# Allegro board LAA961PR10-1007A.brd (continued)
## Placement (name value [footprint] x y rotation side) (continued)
PC111  680P_0603_50V7K  [C_0603]  41.6 23.22 0 top
PC113  220U_6.3V_M  [C_APXK6R3ARA221MF451]  35.39 28.88 0 bottom
PC114  680P_0603_50V7K  [C_0603]  48.36 20.76 180 bottom
PC115  220U_6.3V_M  [C_APXK6R3ARA221MF451]  60.24 14.86 90 bottom
PC117  0.1U_0603_25V7K  [C_0603]  45.46 22.03 270 top
PC118  4.7U_0603_10V6K  [C_0603]  46.69 22.03 270 top
PC119  1U_0603_10V6K  [C_0603]  51.44 28.38 90 top
PC200  10U_0805_25V6K  [C_0805]  92.56 15.19 90 top
PC201  10U_0805_25V6K  [C_0805]  90.85 15.19 90 top
PC203  2200P_0402_50V7K  [C_0402]  93.96 15.9 90 top
PC204  0.22U_0603_16V7K  [C_0603]  82.68 17.75 180 bottom
PC205  22U_0805_6.3V6M  [C_0805]  80.67 15.13 270 bottom
PC206  0.1U_0402_25V6  [C_0402]  94.86 15.9 90 top
PC207  220U_D2_2VY_R17M  [C_D2]  111.06 15.24 0 bottom
PC208  680P_0603_50V7K  [C_0603]  83.64 13.62 0 bottom
PC209  1U_0603_10V6K  [C_0603]  76.11 21.42 270 bottom
PC211  1U_0603_10V6K  [C_0603]  74.84 20.02 90 bottom
PC212  0.033U_0402_16V7K  [C_0402]  74.84 14.2 270 bottom
PC213  100P_0402_50V8J  [C_0402]  71.83 14.21 180 bottom
PC214  .1U_0402_16V7K  [C_0402]  69.95 14.21 270 bottom
PC215  .1U_0402_16V7K  [C_0402]  73.18 18.11 180 bottom
PC300  2200P_0402_50V7K  [C_0402]  192.86 68.38 90 top
PC301  680P_0603_50V7K  [C_0603]  186.18 70.35 0 top
PC302  0.1U_0603_25V7K  [C_0603]  191.65 67.43 90 top
PC303  10U_0805_25V6K  [C_0805]  192.93 68.38 90 bottom
PC304  330P_0402_50V7K  [C_0402]  194.4 63.41 0 bottom
PC305  47U_0805_6.3V6M  [C_0805]  181.08 62.25 270 bottom
PC306  47U_0805_6.3V6M  [C_0805]  182.98 62.25 270 bottom
PC307  22U_0805_6.3VAM  [C_0805]  177.21 62.25 270 bottom
PC308  22U_0805_6.3VAM  [C_0805]  179.24 62.25 270 bottom
PC309  4.7U_0603_6.3V6K  [C_0603]  190.57 64.38 0 top
PC310  4.7U_0603_6.3V6K  [C_0603]  192.92 67.3 270 bottom
PC311  0.1U_0402_25V6  [C_0402]  195.35 66.27 180 bottom
PC400  1U_0402_6.3V6K  [C_0402]  195.11 77.66 270 bottom
PC401  4.7U_0805_6.3V6K  [C_0805]  197.89 77.08 180 bottom
PC402  .1U_0402_16V7K  [C_0402]  192.48 79.58 180 bottom
PC403  0.01U_0402_25V7K  [C_0402]  193.86 87.35 180 bottom
PC404  22U_0805_6.3V6M  [C_0805]  195.27 86.48 90 bottom
PC500  4700P_0603_50V7K  [C_0603]  89.92 98.86 0 top
PC501  .1U_0402_16V7K  [C_0402]  92.89 99.56 0 bottom
PC502  0.068U_0402_16V7K  [C_0402]  90.24 95.55 90 bottom
PC503  1000P_0402_50V7K  [C_0402]  93.59 110.23 0 bottom
PC504  0.1U_0402_25V6  [C_0402]  93.33 112.44 0 bottom
PC505  1U_0603_10V6K  [C_0603]  87.44 100.96 90 top
PC506  100P_0402_50V8J  [C_0402]  84.65 96.37 90 bottom
PC507  0.33U_0603_10V7K  [C_0603]  87.7 98.61 180 top
PC508  680P_0603_50V7K  [C_0603]  101.84 106.94 180 top
PC509  1U_0603_10V7K  [C_0603]  101.73 113.19 180 bottom
PC510  1U_0603_10V7K  [C_0603]  86.24 100.32 180 top
PC511  0.1U_0402_25V6  [C_0402]  82.43 102.53 90 bottom
PC512  1500P_0402_50V7K  [C_0402]  84.78 98.56 270 top
PC513  0.068U_0402_16V7K  [C_0402]  91.13 95.55 90 bottom
PC514  47P_0402_50V8J  [C_0402]  83.76 99.93 90 top
PC515  10U_0805_25V6K  [C_0805]  93.68 107.01 270 bottom
PC516  10U_0805_25V6K  [C_0805]  94.68 107.01 270 top
PC517  10U_0805_25V6K  [C_0805]  92.97 107.01 270 top
PC518  10U_0805_25V6K  [C_0805]  95.39 107.01 270 bottom
PC519  100U_D_20VM_R55M  [C_D]  90.2 106.99 90 bottom
PC520  2200P_0402_50V7K  [C_0402]  86.9 110.61 90 bottom
PC521  0.1U_0402_25V6  [C_0402]  94.5 109.35 180 bottom
PC700  0.1U_0603_25V7K  [C_0603]  52.54 42.61 270 top
PC701  1U_0603_25V6K  [C_0603]  39.88 41.72 0 top
PC702  0.1U_0402_25V6  [C_0402]  41.32 41.91 90 bottom
PC703  0.1U_0402_25V6  [C_0402]  41.29 42.83 180 top
PC704  10U_0805_25V6K  [C_0805]  17.92 51.82 90 top
PC705  10U_0805_25V6K  [C_0805]  19.62 51.82 90 top
PC706  10U_0805_25V6K  [C_0805]  21.32 51.82 90 top
PC707  10U_0805_25V6K  [C_0805]  23.02 51.82 90 top
PC708  22U_0805_25V6M  [C_0805]  24.74 51.83 90 top
PC709  10U_0805_25V6K  [C_0805]  41.85 44.02 90 top
PC710  1U_0603_10V6K  [C_0603]  35.78 45.85 180 bottom
PC711  0.1U_0402_25V6  [C_0402]  41.29 40.16 0 bottom
PC712  0.047U_0603_25V7K~D  [C_0603]  39.32 46.1 270 bottom
PC713  2200P_0402_50V7K  [C_0402]  38.66 55.13 180 top
PC714  22U_0805_25V6M  [C_0805]  38.85 53.81 180 top
PC715  22U_0805_25V6M  [C_0805]  38.86 50.4 180 top
PC716  22U_0805_25V6M  [C_0805]  41.85 47.43 270 bottom
PC717  22U_0805_25V6M  [C_0805]  38.86 52.1 180 top
PC718  100P_0402_50V8J  [C_0402]  42.2 38.41 180 bottom
PC719  100P_0402_50V8J  [C_0402]  39.62 39.6 270 top
PC721  1000P_0603_50V7K  [C_0603]  29.23 53.83 90 top
PC722  0.1U_0603_25V7K  [C_0603]  17.52 60.11 0 top
PC723  10U_0805_25V6K  [C_0805]  17.69 58.64 0 top
PC724  10U_0805_25V6K  [C_0805]  17.69 56.85 0 top
PC725  10U_0805_25V6K  [C_0805]  17.66 55.02 0 top
PC726  0.1U_0402_25V6  [C_0402]  36.44 42 180 top
PC727  0.1U_0402_25V6  [C_0402]  32.9 43.39 270 top
PC728  0.1U_0402_25V6  [C_0402]  35.52 41.11 0 top
PC729  1U_0603_25V6K  [C_0603]  35.59 40.07 0 top
PC732  0.1U_0402_25V6  [C_0402]  38.66 56.02 180 top
PC737  100P_0402_50V8J  [C_0402]  37.53 36.21 270 bottom
PC741  100P_0402_50V8J  [C_0402]  36.65 35.3 90 bottom
PC805  0.1U_0402_10V7K  [C_0402]  10.06 40.92 270 top
PC807  0.47U_0805_25V6K  [C_0805]  207.52 16.91 270 bottom
PC809  1500P_0402_50V7K  [C_0402]  196.45 15.22 0 bottom
PC810  0.1U_0402_10V7K  [C_0402]  7.69 24.07 270 top
PC813  0.1U_0603_50V4Z  [C_0603]  18.85 30.38 270 top
PC815  0.1U_0603_25V7K  [C_0603]  20.06 30.38 270 top
PC816  0.047U_0603_25V7M  [C_0603]  26.11 33.51 270 top
PC817  0.1U_0402_25V4Z~D  [C_0402]  26.05 34.46 0 top
PC900  22U_0805_6.3V6M  [C_0805]  98.36 97.36 0 bottom
PC901  22U_0805_6.3V6M  [C_0805]  101.65 97.35 0 bottom
PC902  22U_0805_6.3V6M  [C_0805]  104.99 97.36 0 bottom
PC903  22U_0805_6.3V6M  [C_0805]  108.41 97.34 0 bottom
PC904  22U_0805_6.3V6M  [C_0805]  111.61 97.34 0 bottom
PC913  22U_0805_6.3V6M  [C_0805]  114.85 99.5 0 bottom
PC914  22U_0805_6.3V6M  [C_0805]  118.15 99.5 0 bottom
PC915  22U_0805_6.3V6M  [C_0805]  104.96 99.57 0 bottom
PC916  22U_0805_6.3V6M  [C_0805]  108.26 99.61 0 bottom
PC917  22U_0805_6.3V6M  [C_0805]  111.66 99.52 0 bottom
PC966  220U 2.5V Y D2 ESR9M H1.9 SX  [C_D2]  113.88 102.75 0 bottom
PD1  -  [TVNST52302AB0_SOT523-3]  154.74 14.79 180 bottom
PD2  -  [TVNST52302AB0_SOT523-3]  152.75 14.79 180 bottom
PD3  BAS40CW SOT-323  [BAS40-05W_SC70-3]  214.25 51.87 90 bottom
PD4  SDMK0340L-7-F_SOD323-2~D  [RB751V-40_SOD323-2]  150.73 15.64 270 bottom
PD5  PESD5V0U2BT_SOT23-3  [AZC199-02SPR7G_SOT23-3]  67.92 119.84 90 bottom
PD702  SDMK0340L-7-F_SOD323-2~D  [SDMK0340L-7-F_SOD323-2]  45.99 46.74 180 top
PD704  SDMK0340L-7-F_SOD323-2~D  [SDMK0340L-7-F_SOD323-2]  49.74 46.68 270 top
PD705  SDMK0340L-7-F_SOD323-2~D  [SDMK0340L-7-F_SOD323-2]  48.01 46.68 270 top
PD800  -  [PDS5100H-13_POWERDI5-3]  10.53 55.59 270 bottom
PD808  -  [PDS5100H-13_POWERDI5-3]  202.59 18.7 180 top
PD813  SDMK0340L-7-F_SOD323-2~D  [SDMK0340L-7-F_SOD323-2]  4.03 27 0 top
PD815  -  [BAT54CW_SOT323-3]  17.34 42.33 180 top
PD817  -  [BAT54CW_SOT323-3]  11.03 33.96 90 top
PH500  100K_0402_1%_NCP15WF104F03RC  [R_0402]  99.49 107.2 0 bottom
PH501  10K_0402_1%_TSM0A103F34D1RZ  [R_0402]  108.13 106.61 0 top
PJP1  PAD-OPEN 1x3m  [JUMP_43X118]  73.79 104.95 270 bottom
PJP5  PAD-OPEN1x1m  [JUMP_43X39]  217.35 107.34 90 bottom
PJP6  PAD-OPEN1x2m  [JUMP_43X79]  214.37 64.12 270 top
PJP9  PAD-OPEN1X2m  [JUMP_43X79]  214.99 59.69 90 top
PJP10  PAD-OPEN1x1m  [JUMP_43X39]  196.71 72.76 0 top
PJP11  PAD-OPEN1x1m  [JUMP_43X39]  176.89 57.33 0 top
PJP12  PAD-OPEN1x1m  [JUMP_43X39]  196.36 112.25 270 top
PJP13  PAD-OPEN1x3m  [JUMP_43X118]  192.61 48.39 90 top
PJP14  PAD-OPEN1x1m  [JUMP_43X39]  174.06 104.52 270 top
PJP15  PAD-OPEN1x1m  [JUMP_43X39]  214.51 83.43 90 top
PJP16  PAD-OPEN1x1m  [JUMP_43X39]  200.85 60.57 270 top
PJP17  PAD-OPEN1x1m  [JUMP_43X39]  199.34 105.65 180 top
PJP19  PAD-OPEN1x1m  [JUMP_43X39]  201.56 30.66 180 top
PJP21  PAD-OPEN1x3m  [JUMP_43X118]  54.5 56.57 90 top
PJP22  PAD-OPEN1x3m  [JUMP_43X118]  56.97 64.19 90 top
PJP23  PAD-OPEN1x1m  [JUMP_43X39]  123.5 56.26 90 top
PJP24  PAD-OPEN1x1m  [JUMP_43X39]  140.15 99.63 270 bottom
PJP25  PAD-OPEN1x1m  [JUMP_43X39]  134.81 109.54 270 bottom
PJP26  PAD-OPEN1x1m  [JUMP_43X39]  22.01 10.18 180 top
PJP27  PAD-OPEN1x1m  [JUMP_43X39]  135.58 106.15 90 bottom
PJP28  PAD-OPEN1x1m  [JUMP_43X39]  143.66 97.76 90 bottom
PJP29  PAD-OPEN1x1m  [JUMP_43X39]  134.24 94.94 270 top
PJP32  PAD-OPEN1x3m  [JUMP_43X118]  187.35 49.49 270 top
PJP36  PAD-OPEN1x1m  [JUMP_43X39]  133.72 106.32 180 top
PJP51  PAD-OPEN1x1m  [JUMP_43X39]  129.85 100.61 180 top
PJP66  PAD-OPEN1x1m  [JUMP_43X39]  201.62 107.51 90 top
PJP100  PAD-OPEN 1x3m  [JUMP_43X118]  37.76 15.54 0 bottom
PJP101  PAD-OPEN 1x3m  [JUMP_43X118]  65.23 19.09 0 bottom
PJP102  PAD-OPEN 1x3m  [JUMP_43X118]  35.96 28.59 90 top
PJP200  PAD-OPEN 1x2m~D  [JUMP_43X79]  91.95 12.39 90 top
PJP201  PAD-OPEN1x1m  [JUMP_43X39]  81.41 16.69 0 top
PJP202  PAD-OPEN1x1m  [JUMP_43X39]  76.55 13.9 270 bottom
PJP203  JUMP_1x3m  [JUMP_43X118]  108.27 18.94 90 bottom
PJP204  JUMP_1x3m  [JUMP_43X118]  112.65 18.94 90 bottom
PJP300  -  [JUMP_43X118]  173.7 62.21 180 bottom
PJP302  PAD-OPEN 1x2m~D  [JUMP_43X79]  196.03 68.7 180 bottom
PJP400  PAD-OPEN1x1m  [JUMP_43X39]  197.3 74.46 90 bottom
PJP401  PAD-OPEN1x1m  [JUMP_43X39]  196.84 86.8 0 bottom
PJP500  PAD-OPEN 4x4m  [JUMP_43X118]  79.26 101.92 90 bottom
PJP700  PAD-OPEN 4x4m  [JUMP_43X118-NPM]  43.96 50.68 180 bottom
PJP701  PAD-OPEN1x1m  [JUMP_43X39]  35.05 43.59 180 top
PJPDC1  ACES_50299-0050N-001  [ACES_50299-0050N-001_5P]  81.55 116.15 270 bottom
PL1  FBMJ4516HS720NT_2P~D  [TAIYO_FBMJ4516HS720NT_2P]  156.93 14.02 0 bottom
PL2  FBMJ4516HS720NT_2P~D  [TAIYO_FBMJ4516HS720NT_2P]  156.93 16.41 0 bottom
PL3  BLM15AG102SN1D_2P  [MURAT_BLM15AG102SN1D_2P]  77.83 113.45 90 top
PL4  FBMJ4516HS720NT_2P  [TAIYO_FBMJ4516HS720NT_2P]  69.34 105.34 270 bottom
PL100  1UH +-20% 6.6A  [L_5X5X3_M_2P-NPM]  36.13 15.48 0 bottom
PL101  2.2UH_7.8A_20%  [PANAS_ETQP3W2R2WFN_2P]  36.18 21.83 180 bottom
PL102  3.3UH_6.3A_20%  [PANAS_ETQP3W2R2WFN_2P]  48.65 16.34 180 bottom
PL200  1UH_11A_20%  [PANAS_ETQP3W2R2WFN_2P]  93.53 16.37 0 bottom
PL301  0.68UH +-20% 7.9A  [L_5X5X3_M_2P]  185.99 67.43 180 bottom
PL500  0.15UH_PCME064T-R15MS0R667_36A_20%  [PANAS_ETQP4LR15AFM_4P]  111.92 108.78 180 bottom
PL501  FBMA-L11-453215800LMA90T_2P  [FBMA-L11-453215800LMA90T_2P-NPM]  79.27 100.56 90 bottom
PL700  1UH +-20% 6.6A  [L_5X5X3_M_2P]  41.28 50.68 0 bottom
PL701  3.3UH +-20% PIMB104T 10A  [TOKO_FDVE1040-H-3R3M-P3_2P]  20.31 47.98 0 bottom
PQ1  DMG2301U-7 1P SOT23-3  [FDN338P_NL_SOT23-3]  147.67 14.15 180 bottom
PQ2  -  [FDV301N-G_SOT23-3]  70.98 112.27 0 top
PQ3  MMST3904-7-F_SOT323~D  [MMST3904-7-F_SOT323-3]  71.64 110.22 180 top
PQ4  -  [FDMC6679AZ_MLP8-5]  48.38 41.01 270 bottom
PQ6  DCX124EK-7-F PNP/NPN_SC74-6~D  [IMD2AT-108_SC74-6]  69.28 96.07 270 top
PQ100  -  [SIS412DN-T1-GE3_POWERPAK8-5]  39.11 20.18 180 top
PQ101  -  [SIS412DN-T1-GE3_POWERPAK8-5]  53.19 16.36 180 top
PQ102  -  [SI7716ADN-T1-GE3_POWERPAK8-5]  43.58 19.82 90 top
PQ103  -  [SI7716ADN-T1-GE3_POWERPAK8-5]  48.03 20.09 270 top
PQ200  -  [SIS412DN-T1-GE3_POWERPAK8-5]  85.95 19.12 180 top
PQ201  -  [SI7716ADN-T1-GE3_POWERPAK8-5]  90.55 18.99 90 top
PQ700  -  [SI4835DDY-T1-GE3_SO8]  49.38 46.79 270 bottom
PQ701  -  [NTR4502PT1G_SOT23-3]  53.65 38.73 90 top
PQ702  -  [NTR4502PT1G_SOT23-3]  53.74 34.74 90 top
PQ703  SI3993CDV-T1-GE3_TSOP6  [NTGD4161PT1G_TSOP6]  59.11 43.06 180 top
PQ705  -  [AON6970_DFN5X6D-8-7]  37.59 47.14 180 bottom
PQ712  -  [DMN65D8LW-7_SOT323-3]  7.44 21 270 top
PQ800  -  [SI4835DDY-T1-GE3_SO8]  14.29 57.53 180 top
PQ806  -  [DMN65D8LDW-7_SOT363-6]  11 37.15 270 top
PQ810  -  [FDS6679AZ-G_SO8]  205.37 21.14 270 bottom
PQ813  -  [DMN65D8LDW-7_SOT363-6]  12.01 29.52 0 top
PQ814  -  [NTR4502PT1G_SOT23-3]  6.86 30.19 270 top
PQ815  -  [FDS6679AZ-G_SO8]  197.81 21.14 270 bottom
PQ816  -  [DMN65D8LW-7_SOT323-3]  201.87 9.62 0 top
PQ817  -  [DMN65D8LDW-7_SOT363-6]  13.72 23.2 90 top
PQ826  -  [FDMC6679AZ_MLP8-5]  198.81 24.64 270 top
PQ829  DMG2301U-7 1P SOT23-3  [SI2301CDS-T1-GE3_SOT23-3]  9.29 34.15 90 top
PQ832  -  [DMN65D8LW-7_SOT323-3]  4.41 35.55 0 top
PR1  1K_0402_5%  [R_0402]  213.27 50.16 180 bottom
PR2  100K_0402_5%  [R_0402]  150.09 16.97 0 bottom
PR6  0_0402_5%  [R0402_0OHM]  146.08 18.05 0 bottom
PR7  0_0402_5%  [R_0402]  68.47 113.41 90 top
PR8  2.2K_0402_5%  [R_0402]  71.25 118.04 0 top
PR9  33_0402_5%  [R_0402]  71.24 117.1 0 top
PR10  100K_0402_1%  [R_0402]  69.38 110.56 90 top
PR11  10K_0402_1%  [R_0402]  74.05 116.17 180 top
PR12  15K_0402_1%  [R_0402]  69.38 108.78 90 top
PR13  10K_0402_5%  [R_0402]  72.15 116.2 180 top
PR14  1M_0402_5%  [R_0402]  70.98 101.02 0 top
PR15  100K_0402_5%  [R_0402]  46.09 40.69 0 top
PR16  4.7K_0805_5%  [R_0805]  68.39 101.18 90 top
PR17  10K_0402_5%  [R_0402]  71.9 101.91 180 top
PR18  1M_0402_5%  [R_0402]  73.27 97.97 0 top
PR100  6.49K_0402_1%  [R_0402]  44.52 29.2 270 top
PR101  15K_0402_1%  [R_0402]  49.44 28.9 90 top
PR102  10K_0402_1%  [R_0402]  45.42 29.01 270 top
PR103  0_0402_5%  [R0402_0OHM]  47.67 29.78 270 top
PR104  10K_0402_1%  [R_0402]  48.55 28.32 90 top
PR105  20K_0402_1%  [R_0402]  43.63 29.19 270 top
PR106  16.9K_0402_1%  [R_0402]  50.33 29.85 270 top
PR107  100K_0402_1%  [R_0402]  42.65 29.16 180 top
PR108  0_0402_5%  [R0402_0OHM]  41.73 28.27 0 top
PR109  2.2_0603_5%  [R_0603]  50.99 24.76 0 top
PR110  2.2_0603_5%  [R_0603]  41.54 24.92 0 top
PR111  4.7_1206_5%  [R_1206]  37.67 24.22 0 top
PR112  4.7_1206_5%  [R_1206]  52.21 20.89 180 bottom
PR113  0_0402_5%  [R0402_0OHM]  52.52 29.14 270 top
PR114  200_0402_1%  [R_0402]  50.92 27.17 0 top
PR200  2.2_0603_5%  [R_0603]  82.69 16.49 180 bottom
PR201  19.6K_0402_1%  [R_0402]  77.21 21.45 270 bottom
PR202  5.1_0603_5%  [R_0603]  72.91 19.7 0 top
PR203  4.7_1206_5%  [R_1206]  84.57 17.72 270 bottom
PR204  0_0603_5%  [R_0603]  76.9 19.61 180 top
PR205  8.06K_0402_1%  [R_0402]  71.83 15.1 180 bottom
PR206  768K_0402_1%  [R_0402]  72.27 20.78 0 bottom
PR207  0_0402_5%  [R0402_0OHM]  73.18 19.89 270 bottom
PR209  10K_0402_1%  [R_0402]  71.83 13.33 180 bottom
PR210  0_0402_5%  [R0402_0OHM]  72.27 17.22 0 bottom
PR303  1M_0402_1%  [R_0402]  187.13 64.04 270 bottom
PR305  4.7_1206_5%  [R_1206]  186.63 68.6 180 top
PR306  0_0402_5%  [R_0402]  190.69 63.4 90 bottom
PR307  7.5K_0402_1%  [R_0402]  193.46 63.41 90 bottom
PR308  0_0402_5%  [R_0402]  191.63 64.3 270 bottom
PR309  1K_0402_5%  [R_0402]  195.29 64.29 180 bottom
PR310  10K_0402_1%  [R_0402]  192.59 64.32 270 bottom
PR312  0_0603_5%  [R_0603]  190.5 68.7 180 top
PR313  0_0402_5%  [R0402_0OHM]  188.9 63.12 90 bottom
PR315  100K_0402_1%  [R_0402]  189.8 63.12 90 bottom
PR400  100K_0402_5%  [R_0402]  191.57 77.78 0 bottom
PR401  47K_0402_5%  [R_0402]  192.48 78.68 180 bottom
PR402  8.66K_0402_1%  [R_0402]  193.86 86.43 180 bottom
PR403  10K_0402_1%  [R_0402]  192.03 87.38 270 bottom
PR500  75_0402_1%  [R_0402]  92.89 98.16 0 bottom
PR501  365K_0402_1%  [R_0402]  92.84 99.38 270 top
PR502  75_0402_1%  [R_0402]  92.89 101.4 0 bottom
PR503  681K_0402_1%  [R_0402]  92.89 102.29 0 bottom
PR504  36.5K_0402_1%  [R_0402]  92.89 103.18 0 bottom
PR505  10K_0402_5%  [R_0402]  93.8 101.4 180 top
PR506  39K_0402_1%  [R_0402]  90.16 99.94 0 top
PR507  150K_0402_1%  [R_0402]  90.16 100.83 0 top
PR508  100K_0402_1%  [R_0402]  90.16 101.72 0 top
PR509  20K_0402_1%  [R_0402]  90.16 102.61 0 top
PR510  39K_0402_5%~N  [R_0402]  90.22 97.78 0 top
PR511  10K_0402_5%  [R_0402]  93.8 97.27 180 bottom
PR512  2.15K_0402_1%  [R_0402]  107.25 107.48 90 top
PR513  75_0402_1%  [R_0402]  88.52 102.37 270 top
PR514  20K_0402_1%  [R_0402]  108.14 107.48 90 top
PR515  3.01K_0402_1%  [R_0402]  109.03 107.48 90 top
PR516  1.91K_0402_1%  [R_0402]  88.14 103.42 90 bottom
PR517  2.2_0603_5%  [R_0603]  94.48 111.31 180 bottom
PR518  2M_0402_1%  [R_0402]  95.07 101.43 270 top
PR519  1_0603_5%  [R_0603]  87.19 104.24 180 bottom
PR520  0_0402_5%  [R0402_0OHM]  90.16 104.33 270 bottom
PR521  4.87K_0402_1%  [R_0402]  84.88 98.59 90 bottom
PR522  4.7_1206_5%  [R_1206]  102.3 110.93 270 top
PR523  10K_0402_5%  [R_0402]  83.76 96.37 90 bottom
PR524  2M_0402_1%  [R_0402]  95.96 99.62 180 top
PR525  27K_0402_1%  [R_0402]  95.96 100.51 90 top
PR526  10_0603_1%  [R_0603]  83.82 99.61 270 bottom
PR527  54.9_0402_1%  [R_0402]  83.3 102.04 0 bottom
PR528  75_0402_1%  [R_0402]  83.3 102.92 0 bottom
PR529  110_0402_1%  [R_0402]  83.3 103.84 0 bottom
PR531  0_0402_5%  [R0402_0OHM]  97.86 95.48 90 top
PR532  0_0402_5%  [R0402_0OHM]  96.97 95.48 90 top
PR534  0_0402_5%  [R0402_0OHM]  82.41 100.28 90 bottom
PR535  4.75K_0402_1%  [R_0402]  83.89 97.64 90 top
PR536  0_0402_5%  [R0402_0OHM]  90.05 104.4 270 top
PR539  0_0402_5%  [R0402_0OHM]  88.14 103.94 90 top
PR700  0_0402_5%  [R0402_0OHM]  49.98 48.43 90 bottom
PR701  0.01_1206_1%  [R_1206_4P-D]  48.49 53.36 270 bottom
PR702  0_0402_5%  [R0402_0OHM]  51.5 42.14 270 top
PR703  100_0402_1%  [R_0402]  44.34 42.84 270 top
PR704  0_0402_5%  [R0402_0OHM]  43.48 41.93 180 top
PR705  0_0402_5%  [R0402_0OHM]  43.48 42.82 180 top
PR706  100K_0402_1%  [R_0402]  55.95 41.16 270 top
PR707  100K_0402_1%  [R_0402]  55.92 42.59 90 top
PR708  10_1206_5%  [R_1206]  46.12 44.81 180 top
PR709  0_0402_5%  [R0402_0OHM]  56.11 44.45 0 top
PR710  34K_0402_1%  [R_0402]  42.19 41.04 180 bottom
PR711  6.49K_0402_1%  [R_0402]  41.29 39.28 0 bottom
PR712  2.2_0603_5%  [R_0603]  36.83 45.79 0 bottom
PR713  100K_0402_1%  [R_0402]  41.49 37.7 90 top
PR714  0_0402_5%  [R0402_0OHM]  41.48 39.68 90 top
PR715  154K_0402_1%  [R_0402]  40.54 38.66 90 top
PR716  0_0402_5%  [R0402_0OHM]  42.28 37.53 180 bottom
PR717  0_0402_5%  [R0402_0OHM]  39.69 37.23 180 bottom
PR718  0_0402_5%  [R0402_0OHM]  39.63 36.36 90 top
PR720  0_0402_5%  [R0402_0OHM]  38.74 36.36 90 top
PR721  0.01_1206_1%  [R_1206_4P-D]  16.5 53.72 270 bottom
PR722  4.02K_0402_1%  [R_0402]  33.54 41.61 180 top
PR723  10_0603_1%  [R_0603]  34.08 40.55 180 top
PR725  1K_0402_1%  [R_0402]  33.23 39.51 0 top
PR726  4.7_1206_5%  [R_1206]  30.51 54.36 0 top
PR728  0_0402_5%  [R0402_0OHM]  33.23 38.64 0 top
PR729  154K_0402_1%  [R_0402]  35.55 39.03 0 top
PR737  649K_0402_1%  [R_0402]  39.32 35.29 90 bottom
PR738  3M_0402_5%  [R_0402]  37.54 37.22 180 bottom
PR740  10K_0402_1%  [R_0402]  35.79 36.36 180 bottom
PR743  0_0402_5%  [R0402_0OHM]  35.79 37.23 180 bottom
PR745  100K_0402_1%  [R_0402]  38.44 36.2 270 bottom
PR788  20K_0402_1%  [R_0402]  38.74 39.6 270 top
PR799  10K_0402_1%  [R_0402]  34.06 42.71 180 bottom
PR810  100K_0402_5%  [R_0402]  9.98 38.99 270 top
PR811  0_0402_5%  [R0402_0OHM]  206.01 15.97 270 bottom
PR812  0_0402_5%  [R0402_0OHM]  5.88 37.43 90 top
PR813  100K_0402_5%  [R_0402]  204.74 16.13 180 bottom
PR814  330K_0402_5%  [R_0402]  201.95 16.12 180 bottom
PR815  100K_0402_5%  [R_0402]  204.74 15.05 180 bottom
PR816  0_0402_5%  [R_0402]  204.24 14.2 270 bottom
PR818  100K_0402_5%  [R_0402]  197.35 16.13 180 bottom
PR819  100K_0402_5%  [R_0402]  12.25 21.81 0 top
PR822  10K_0402_5%  [R_0402]  197.37 14.24 270 bottom
PR826  100K_0402_5%  [R_0402]  10.7 29.95 270 top
PR827  100K_0402_5%  [R_0402]  10.7 30.88 90 top
PR828  10K_0402_5%  [R_0402]  5.46 32.57 270 top
PR829  100K_0402_5%  [R_0402]  13.4 27.16 90 top
PR830  100K_0402_5%  [R_0402]  7.1 36.55 180 top
PR831  100_0603_1%  [R_0603]  14.73 34.31 0 top
PR832  100_0603_1%  [R_0603]  15.84 35.42 90 top
PR835  47_0805_5%~D  [R_0805]  17.35 28.58 90 top
PR838  100_0603_1%  [R_0603]  15.83 37.8 90 top
PR842  0_0402_5%  [R0402_0OHM]  21.14 29.54 90 top
PR843  0_0402_5%  [R0402_0OHM]  18.3 40.62 90 top
PR844  10K_0402_5%  [R_0402]  15.62 42.54 90 top
PR845  0_0402_5%  [R0402_0OHM]  19.19 40.62 90 top
PR846  100K_0402_5%  [R_0402]  22.16 28.12 180 top
PR847  100_0603_1%  [R_0603]  22.19 29.45 90 top
PR848  0_0402_5%  [R0402_0OHM]  20.78 40.61 90 top
PR850  0_0402_5%  [R0402_0OHM]  22.56 40.61 90 top
PR851  0_0402_5%  [R0402_0OHM]  23.26 29.61 90 top
PR853  0_0402_5%  [R0402_0OHM]  11.61 28.06 0 top
PR854  0_0402_5%  [R0402_0OHM]  23.47 40.61 90 top
PR855  0_0402_5%  [R0402_0OHM]  24.15 29.61 90 top
PR857  0_0402_5%  [R0402_0OHM]  25.97 38.76 0 top
PR858  1M_0402_5%  [R_0402]  21.67 41.52 270 top
PR859  0_0402_5%  [R0402_0OHM]  25.97 39.64 0 top
PR860  100_0603_1%  [R_0603]  26.08 36.81 0 top
PR863  0_0402_5%  [R_0402]  24.4 40.59 90 top
PR864  100K_0402_5%  [R_0402]  23.29 28.12 0 top
PR874  1M_0402_5%  [R_0402]  25.97 37.87 0 top
PR895  0_0402_5%  [R0402_0OHM]  8.88 36.55 180 top
PRP2  100_0804_8P4R_5%  [RP_0804_8P4R]  156.56 19.73 180 bottom
PT1  PAD~D  [TPC12]  190.74 88.93 0 top
PT2  PAD~D  [TPC12]  190.19 90.1 0 top
PT3  PAD~D  [TPC12]  202.31 107.79 180 bottom
PU1  TS5A63157DCKR_SC70-6~D  [TS5A63157DCKR_SC70-6]  68.66 116.38 0 top
PU100  -  [TPS51285BRUKR_QFN20_3X3]  47.54 26.56 180 top
PU200  -  [RT8207MZQW_WQFN20_3X3]  78.15 15.51 180 bottom
PU300  -  [SYX198DQNC_QFN10_3X3]  188.88 66.54 0 bottom
PU400  -  [APL5930KAI-TRG_SO8]  193.8 84.45 0 bottom
PU500  TPS51624RSM_QFN32_4X4  [TPS51622RSM_QFN32_4X4]  87.35 102.14 0 bottom
PU501  -  [CSD97374CQ4M_SON8_3P5X4P5]  99.32 111.72 270 bottom
PU700  BQ24777RUYR_WQFN28_4x4  [BQ24715URUYR_WQFN28_4X4]  39.77 42.29 180 bottom
PU800  CD3301BRHHR_QFN36_6X6~D  [CD3301RHHR_QFN36_6X6]  18.91 32.64 0 top
PU804  TC7SH08FU_SSOP5~D  [TC7SH08FU_SSOP5]  6.95 38.87 270 top
PU806  TC7SH08FU_SSOP5~D  [TC7SH08FU_SSOP5]  10.72 23.23 90 top
QA1  -  [L2N7002WT1G_SC-70-3]  201.12 65.02 0 top
QA2  -  [DMN66D0LDW-7_SOT363-6]  217.94 75.77 0 top
QA3  -  [DMN66D0LDW-7_SOT363-6]  208.11 60.59 90 top
QC1  -  [DMN66D0LDW-7_SOT363-6]  158.06 68.43 90 bottom
QD1  -  [L2N7002WT1G_SC-70-3]  98.43 10.21 0 top
QE2  -  [DMN66D0LDW-7_SOT363-6]  194.12 83.76 270 top
QE3  MMBT3904WT1G_SC70-3~D  [MMBT3904WT1G_SC70-3]  113.95 80.69 270 top
QE4  -  [MMBT3904WT1G_SC70-3]  199.9 99.5 90 top
QE5  MMBT3904WT1G_SC70-3~D  [MMBT3904WT1G_SC70-3]  204.43 35.6 180 bottom
QE6  MMBT3904WT1G_SC70-3~D  [MMBT3904WT1G_SC70-3]  84.43 95.56 90 top
QE7  MMBT3904WT1G_SC70-3~D  [MMBT3904WT1G_SC70-3]  195.82 104.23 0 bottom
QL1  -  [DMN66D0LDW-7_SOT363-6]  208.4 124.11 270 top
QL2  -  [DMN66D0LDW-7_SOT363-6]  217.95 122 270 top
QN1  -  [DMN66D0LDW-7_SOT363-6]  215.71 111.72 180 top
QV1  -  [AO6405_TSOP6]  94.69 113.88 180 top
QV2  -  [L2N7002WT1G_SC-70-3]  82.05 112.05 270 top
QV7  -  [L2N7002WT1G_SC-70-3]  125.98 124.12 180 bottom
QV8  -  [LP2301ALT1G_SOT23-3]  122.24 120.64 180 bottom
QV9  -  [L2N7002WT1G_SC-70-3]  136.72 118.99 90 bottom
QV10  -  [L2N7002WT1G_SC-70-3]  161.93 98.8 270 bottom
QV501  -  [L2N7002WT1G_SC-70-3]  241.06 132.26 270 top
QV502  -  [L2N7002WT1G_SC-70-3]  234.51 125.15 0 top
QV700  -  [DMN66D0LDW-7_SOT363-6]  168.75 116.66 90 bottom
QZ1  -  [LP2301ALT1G_SOT23-3]  104.74 119.48 270 top
QZ2  -  [DMN66D0LDW-7_SOT363-6]  163.85 93.85 180 bottom
QZ3  -  [DMN66D0LDW-7_SOT363-6]  191.58 114.48 90 top
QZ4  -  [DDTA114EUA-7-F_SOT323-3]  191.51 112.65 90 top
QZ5  -  [DMN66D0LDW-7_SOT363-6]  190.63 120.13 270 top
QZ6  -  [SI3456DDV-T1-GE3_TSOP6]  133.91 100.71 90 top
QZ7  -  [DMN66D0LDW-7_SOT363-6]  191.9 126.99 270 top
QZ9  -  [DDTA114EUA-7-F_SOT323-3]  199.43 123.71 90 top
QZ10  -  [DMN66D0LDW-7_SOT363-6]  164.35 80.08 0 top
QZ11  -  [DMN66D0LDW-7_SOT363-6]  206.16 54.84 0 bottom
QZ12  -  [DDTA114EUA-7-F_SOT323-3]  198.3 119.48 90 top
QZ14  -  [DMN66D0LDW-7_SOT363-6]  193.61 120.13 270 top
R6  10_0402_5%  [R_0402]  161.36 125.2 270 bottom
R41  10_0402_5%  [R_0402]  165.1 125.23 270 bottom
R252  33_0402_5%  [R_0402]  144.47 124.31 90 bottom
R253  33_0402_5%  [R_0402]  145.35 124.31 90 bottom
R254  33_0402_5%  [R_0402]  146.05 130.43 270 top
R255  33_0402_5%  [R_0402]  146.24 124.31 90 bottom
R256  33_0402_5%  [R_0402]  146.94 130.43 270 top
R257  33_0402_5%  [R_0402]  147.13 124.31 90 bottom
R258  33_0402_5%  [R_0402]  149.61 130.43 270 top
R259  33_0402_5%  [R_0402]  143.58 124.31 90 bottom
R260  33_0402_5%  [R_0402]  144.27 130.43 270 top
R261  33_0402_5%  [R_0402]  145.16 130.43 270 top
R262  33_0402_5%  [R_0402]  147.83 130.43 270 top
R263  33_0402_5%  [R_0402]  148.02 124.31 90 bottom
R264  33_0402_5%  [R_0402]  148.72 130.43 270 top
R265  33_0402_5%  [R_0402]  148.91 124.31 90 bottom
R266  33_0402_5%  [R_0402]  149.8 124.31 90 bottom
R267  33_0402_5%  [R_0402]  150.5 130.43 270 top
R268  100K_0402_5%  [R_0402]  152.21 125.23 270 bottom
R271  100K_0402_5%  [R_0402]  150.51 137.15 180 top
R272  100K_0402_5%  [R_0402]  179.34 124.01 180 bottom
R273  10_0402_5%  [R_0402]  175.47 125.38 270 bottom
RA3  0_0603_5%  [R0603_0OHM]  208.59 77.13 270 top
RA4  0_0603_5%  [R0603_0OHM]  214.72 77.16 270 top
RA5  2.2K_0402_5%  [R_0402]  211.7 68.88 0 top
RA6  2.2K_0402_5%  [R_0402]  211.7 69.75 0 top
RA7  24.9_0402_1%  [R_0402]  211.65 72 0 top
RA8  24.9_0402_1%  [R_0402]  211.65 71.12 0 top
RA9  33_0402_5%  [R_0402]  201.09 69.98 0 top
RA12  1K_0402_5%  [R_0402]  199.8 67.34 180 top
RA13  1K_0402_5%  [R_0402]  199.8 66.47 180 top
RA14  33_0402_5%  [R_0402]  201.69 74.54 180 top
RA17  33_0402_5%  [R_0402]  201.75 71.33 180 top
RA18  10K_0402_5%  [R_0402]  200.28 77.3 180 top
RA21  100K_0402_5%  [R_0402]  215.78 77.4 0 top
RA24  4.7K_0402_5%  [R_0402]  213.39 72 0 top
RA25  4.7K_0402_5%  [R_0402]  213.39 71.12 0 top
RA26  100K_0402_5%  [R_0402]  204.28 61.05 0 top
RA27  200K_0402_5%  [R_0402]  209.96 61.99 180 top
RA28  100K_0402_5%  [R_0402]  204.28 60.16 0 top
RA29  100K_0402_5%  [R_0402]  209.96 61.1 180 top
RA30  22_0402_5%  [R_0402]  203.3 64.91 90 top
RA31  22_0402_5%  [R_0402]  204.18 64.91 90 top
RA32  33_0402_5%  [R_0402]  205.04 64.91 90 top
RA35  0_0402_5%  [R0402_0OHM]  217.44 66.45 0 top
RA36  0_0402_5%  [R0402_0OHM]  220.27 75.56 90 top
RA37  0_0402_5%  [R0402_0OHM]  210.16 63.95 270 top
RA38  100K_0402_5%  [R_0402]  203.41 60.15 90 top
RA39  0_0805_5%  [R0805_0OHM]  200.66 81.32 270 top
RA44  100K_0402_5%  [R_0402]  209.29 62.88 90 top
RA45  0_0402_5%  [R0402_0OHM]  211.05 61.75 270 top
RC1  330K_0402_5%  [R_0402]  163.15 53.95 90 top
RC2  1K_0402_5%  [R_0402]  121.57 14.38 270 bottom
RC4  0_0402_5%  [R0402_0OHM]  142.5 64.2 270 bottom
RC7  10M_0402_5%  [R_0402]  142.5 62.3 270 bottom
RC8  20K_0402_5%  [R_0402]  164.07 65.38 180 top
RC9  1M_0402_5%  [R_0402]  164.07 61.85 180 top
RC10  20K_0402_5%  [R_0402]  164.07 62.73 180 top
RC11  1K_0402_5%  [R_0402]  133.01 61.7 90 bottom
RC17  3.01K_0402_1%  [R_0402]  131 94.34 90 top
RC18  1K_0402_1%  [R_0402]  76.82 76.64 0 top
RC19  33_0402_5%  [R_0402]  134.79 61.7 90 bottom
RC20  33_0402_5%  [R_0402]  164.06 59.79 180 top
RC21  51_0402_5%  [R_0402]  94.41 77.02 180 top
RC22  33_0402_5%  [R_0402]  136.7 61.7 90 bottom
RC23  33_0402_5%  [R_0402]  135.81 61.7 90 bottom
RC25  1K_0402_5%  [R_0402]  93.84 91.91 180 bottom
RC26  0_0402_5%  [R0402_0OHM]  156.85 78.21 90 bottom
RC27  0_0402_5%  [R_0402]  156.91 81.28 270 bottom
RC29  1K_0402_5%  [R_0402]  175.53 76.14 180 top
RC30  0_0402_5%  [R0402_0OHM]  154.8 72.19 0 bottom
RC31  1K_0402_5%  [R_0402]  176.82 76.15 0 top
RC32  0_0402_5%  [R0402_0OHM]  154.8 73.08 0 bottom
RC33  499_0402_1%  [R_0402]  158.27 72.19 180 bottom
RC34  499_0402_1%  [R_0402]  158.27 73.08 180 bottom
RC35  0_0402_5%  [R0402_0OHM]  178.65 76.17 0 top
RC38  33_0402_5%  [R_0402]  180.33 73.19 0 top
RC50  0_0402_5%  [R0402_0OHM]  191.15 75.63 0 top
RC55  33_0402_5%  [R_0402]  191.12 73.7 0 top
RC61  33_0402_5%  [R_0402]  192.04 74.68 180 top
RC62  33_0402_5%  [R_0402]  171.85 73.76 0 top
RC63  1M_0402_5%  [R_0402]  123.36 100.43 90 top
RC65  0_0402_5%  [R0402_0OHM]  123.36 99.13 270 top
RC66  10K_0402_5%  [R_0402]  147.01 78.87 180 bottom
RC67  22_0402_5%  [R_0402]  163.31 55.77 90 top
RC68  10K_0402_5%  [R_0402]  146.93 81.21 180 top
RC69  3.01K_0402_1%  [R_0402]  123.31 95.56 0 bottom
RC70  22_0402_5%  [R_0402]  164.19 55.77 90 top
RC72  22_0402_5%  [R_0402]  164.04 57.98 90 top
RC74  22_0402_5%  [R_0402]  164.91 57.98 90 top
RC77  0_0402_5%  [R0402_0OHM]  158.63 84.78 270 bottom
RC78  330K_0402_5%  [R_0402]  141.52 61.38 90 bottom
RC79  10K_0402_5%  [R_0402]  154.74 61.03 180 bottom
RC80  8.2K_0402_5%  [R_0402]  163.5 84.64 0 bottom
RC81  10K_0402_5%  [R_0402]  154.74 61.92 180 bottom
RC82  10K_0402_5%  [R_0402]  159.77 73.75 0 top
RC87  0_0402_5%  [R0402_0OHM]  161.31 77.93 180 top
RC88  0_0402_5%  [R0402_0OHM]  161.31 77.04 180 top
RC89  0_0402_5%  [R0402_0OHM]  158.61 76.8 0 top
RC91  47K_0402_5%  [R_0402]  164.07 60.72 180 top
RC92  10K_0402_5%  [R_0402]  155.49 73.38 180 top
RC95  8.2K_0402_5%  [R_0402]  168.62 82.92 180 top
RC98  0_0402_5%  [R_0402]  67.41 67.15 180 top
RC99  0_0402_5%  [R_0402]  67.41 70.07 180 top
RC102  1K_0402_5%  [R_0402]  63.63 43.22 90 top
RC103  1K_0402_5%  [R_0402]  64.52 43.22 90 top
RC106  1K_0402_5%  [R_0402]  66.74 56.9 270 top
RC109  0_0402_5%  [R_0402]  60.33 68.65 270 top
RC112  0_0402_5%  [R_0402]  67.41 69.12 180 top
RC113  1K_0402_5%  [R_0402]  70.74 55.92 90 top
RC114  49.9_0402_1%  [R_0402]  87.88 81.59 180 bottom
RC115  0_0402_5%  [R_0402]  66.5 68.16 0 top
RC116  62_0402_5%  [R_0402]  79.9 76.38 180 bottom
RC117  51_0402_5%  [R_0402]  68.77 56.82 270 top
RC118  0_0402_5%  [R_0402]  69.19 67.15 180 top
RC119  0_0402_5%  [R_0402]  68.34 69.12 0 top
RC120  1K_0402_5%  [R_0402]  68.15 38.51 270 top
RC121  56_0402_5%  [R_0402]  78.98 77.4 0 bottom
RC122  1K_0402_5%  [R_0402]  164.42 85.53 180 bottom
RC123  10K_0402_5%  [R_0402]  92.93 93.62 90 top
RC124  51_0402_5%  [R_0402]  92.93 89.08 0 bottom
RC125  51_0402_5%  [R_0402]  92.93 88.19 0 bottom
RC126  51_0402_5%  [R_0402]  94.3 85.55 0 bottom
RC127  51_0402_5%  [R_0402]  92.93 87.3 0 bottom
RC128  51_0402_5%  [R_0402]  82.79 83.8 0 bottom
RC129  51_0402_5%  [R_0402]  83.12 83.19 270 top
RC130  200_0402_1%  [R_0402]  97.14 63 270 bottom
RC131  121_0402_1%  [R_0402]  98.09 63 270 bottom
RC132  100_0402_1%  [R_0402]  96.18 63 270 bottom
RC133  24.9_0402_1%  [R_0402]  126.55 85.33 0 top
RC136  0_0402_5%  [R_0402]  140.86 76.8 0 top
RC139  100K_0402_5%  [R_0402]  135.75 96.7 0 bottom
RC140  1K_0402_5%  [R_0402]  146.51 83.14 180 bottom
RC141  100K_0402_5%  [R_0402]  142.53 95.43 180 bottom
RC142  100K_0402_5%  [R_0402]  142.53 96.32 180 bottom
RC149  3.01K_0402_1%  [R_0402]  121.8 95.48 90 bottom
RC152  22.6_0402_1%  [R_0402]  131.07 75.25 270 top
RC153  10K_0402_5%  [R_0402]  157.12 72.49 90 top
RC155  100K_0402_5%  [R_0402]  167.73 83.92 0 top
RC156  100K_0402_5%  [R_0402]  163.27 89.16 270 top
RC158  100K_0402_5%  [R_0402]  158.7 87.66 0 top
RC160  100K_0402_5%  [R_0402]  158.55 81.82 0 top
RC161  0_0402_5%  [R0402_0OHM]  92.93 90.02 0 bottom
RC163  10K_0402_5%  [R_0402]  156.58 93.93 180 bottom
RC164  10K_0402_5%  [R_0402]  148.05 97.6 270 bottom
RC171  10K_0402_5%  [R_0402]  167.73 84.93 0 top
RC174  100K_0402_5%  [R_0402]  154.4 77.18 0 top
RC175  100K_0402_5%  [R_0402]  161.58 65.48 180 bottom
RC176  1K_0402_5%  [R_0402]  148.92 97.6 270 bottom
RC178  49.9_0402_1%  [R_0402]  132 62.36 270 bottom
RC179  1K_0402_5%  [R_0402]  158.92 73.96 180 top
RC180  1K_0402_5%  [R_0402]  162.82 81.18 0 bottom
RC183  1K_0402_1%  [R_0402]  94.42 76.06 180 top
RC184  1K_0402_1%  [R_0402]  91.12 78.35 180 bottom
RC185  49.9_0402_1%  [R_0402]  90.2 80 0 bottom
RC186  8.2K_0402_1%  [R_0402]  133.02 96.7 0 bottom
RC187  49.9_0402_1%  [R_0402]  131.11 62.36 270 bottom
RC188  1K_0402_1%  [R_0402]  93.45 85.53 180 bottom
RC189  1K_0402_1%  [R_0402]  96.62 79.82 0 top
RC190  1K_0402_1%  [R_0402]  93.5 78.48 0 top
RC191  1K_0402_5%  [R_0402]  99.08 78.44 180 top
RC192  0_0402_5%  [R_0402]  143.87 91.63 270 bottom
RC193  0_0402_5%  [R_0402]  93.84 90.96 180 bottom
RC194  0_0402_5%  [R_0402]  159.6 65.61 0 top
RC195  0_0402_5%  [R_0402]  93.96 64.2 270 bottom
RC196  0_0603_5%  [R_0603]  100.02 95.49 90 top
RC197  150_0402_5%  [R_0402]  64.84 56.37 90 top
RC198  10K_0402_5%  [R_0402]  64.56 41.41 180 top
RC199  10K_0402_5%  [R_0402]  92.89 95.49 0 bottom
RC201  1.5K_0402_5%  [R_0402]  93.84 96.38 0 bottom
RC202  1K_0402_5%  [R_0402]  77.66 82.02 90 top
RC204  75_0402_1%  [R_0402]  89.72 82.34 90 bottom
RC207  43_0402_5%  [R_0402]  93.28 83.62 180 bottom
RC208  110_0402_1%  [R_0402]  88.82 82.34 90 bottom
RC209  100_0402_1%  [R_0402]  98.75 96.4 270 top
RC211  5.11_0402_1%  [R_0402]  126.16 59.22 90 top
RC212  0_0402_5%  [R0402_0OHM]  130.83 59.73 270 top
RC213  0_0402_5%  [R_0402]  130.62 56.81 90 top
RC216  0_0402_5%  [R_0402]  129.95 59.73 270 top
RC217  0_0402_5%  [R0402_0OHM]  129.75 56.81 90 top
RC218  100_0402_1%  [R_0402]  95.95 95.48 90 top
RC219  0_0402_5%  [R0402_0OHM]  158.61 75.92 0 top
RC224  0_0402_5%  [R_0402]  167.26 67.57 270 top
RC225  0_0402_5%  [R_0402]  168.4 67.57 270 top
RC226  0_0402_5%  [R_0402]  169.29 67.63 270 top
RC227  0_0402_5%  [R_0402]  170.37 67.63 270 top
RC228  0_0402_5%  [R_0402]  171.26 67.63 270 top
RC229  0_0402_5%  [R_0402]  172.34 67.63 270 top
RC230  0_0402_5%  [R_0402]  173.36 67.63 270 top
RC231  0_0402_5%  [R_0402]  174.31 66.78 90 top
RC240  10K_0402_5%  [R_0402]  114.98 95.32 270 top
RC241  10K_0402_5%  [R_0402]  116.25 95.32 270 top
RC242  10K_0402_5%  [R_0402]  158 66.55 0 bottom
RC243  10K_0402_5%  [R_0402]  158 65.61 0 bottom
RC245  100K_0402_5%  [R_0402]  161.48 64.63 90 top
RC247  10K_0402_5%  [R_0402]  144.96 88.22 270 top
RC300  10K_0402_5%  [R_0402]  145.94 77.04 180 top
RC301  0_0402_5%  [R0402_0OHM]  128.46 14.42 270 bottom
RC302  10K_0402_5%  [R_0402]  145.85 85.4 270 top
RC303  10K_0402_5%  [R_0402]  144.96 84.48 90 top
RC304  100K_0402_5%  [R_0402]  164.65 82.64 270 bottom
RC305  1K_0402_5%  [R_0402]  96.55 78.46 180 top
RD2  470_0402_5%  [R_0402]  67.63 23.47 90 top
RD3  0_0402_5%  [R0402_0OHM]  66.49 23.47 90 top
RD4  1.8K_0402_1%  [R_0402]  56.53 34.53 180 top
RD5  2_0402_1%  [R_0402]  55.62 35.42 0 top
RD6  1.8K_0402_1%  [R_0402]  55.63 36.3 90 top
RD7  24.9_0402_1%  [R_0402]  56.59 38.09 180 top
RD9  220K_0402_5%  [R_0402]  94.26 9.95 0 top
RD10  66.5_0402_1%  [R_0402]  94.05 20.04 90 top
RD11  66.5_0402_1%  [R_0402]  95.19 20.04 90 top
RD12  66.5_0402_1%  [R_0402]  170.1 20.04 90 top
RD13  66.5_0402_1%  [R_0402]  171.24 20.04 90 top
RD14  2M_0402_5%  [R_0402]  96 8.99 180 top
RD15  0_0402_5%  [R0402_0OHM]  119.27 28.12 90 top
RD16  0_0402_5%  [R0402_0OHM]  120.21 28.11 90 top
RD18  1.8K_0402_1%  [R_0402]  68.58 23.47 90 top
RD19  2_0402_1%  [R_0402]  69.52 24.31 0 top
RD20  1.8K_0402_1%  [R_0402]  69.09 25.25 90 top
RD21  24.9_0402_1%  [R_0402]  72.08 26.2 90 top
RD22  1.8K_0402_1%  [R_0402]  129.61 29.96 90 top
RD23  2_0402_1%  [R_0402]  129.61 32.71 180 top
RD24  1.8K_0402_1%  [R_0402]  129.61 31.79 180 top
RD25  24.9_0402_1%  [R_0402]  127.8 30.85 0 top
RD27  0_0402_5%  [R0402_0OHM]  193.3 35.31 270 top
RD28  0_0402_5%  [R0402_0OHM]  194.31 34.39 90 top
RE5  100K_0402_5%  [R_0402]  189.36 93.2 90 top
RE8  100K_0402_5%  [R_0402]  175.12 105.93 90 top
RE9  100K_0402_5%  [R_0402]  185.61 109.67 270 top
RE10  100K_0402_5%  [R_0402]  184.72 109.67 270 top
RE11  100K_0402_5%  [R_0402]  174.11 99.05 0 top
RE12  100K_0402_5%  [R_0402]  191.79 96.89 180 top
RE17  100K_0402_5%  [R_0402]  183.9 92.56 90 top
RE20  100K_0402_5%  [R_0402]  190.83 99.37 180 top
RE21  10K_0402_5%  [R_0402]  187.39 109.67 270 top
RE24  10K_0402_5%  [R_0402]  178.76 92.97 90 top
RE25  100K_0402_5%  [R_0402]  184.74 115.18 180 top
RE26  10_0402_5%  [R_0402]  184.74 116.06 180 top
RE27  33_0402_5%  [R_0402]  183.01 93.48 270 top
RE31  100K_0402_5%  [R_0402]  215.46 81.59 270 top
RE32  0_0402_5%  [R0402_0OHM]  211.05 84.74 180 top
RE33  10K_0402_5%  [R_0402]  216.41 79.68 0 top
RE35  10K_0402_5%  [R_0402]  172.85 99.24 90 top
RE36  100K_0402_5%  [R_0402]  184.93 92.56 90 top
RE37  2.2K_0402_5%  [R_0402]  203.33 81.32 90 top
RE42  10K_0402_5%  [R_0402]  210.58 79.04 270 top
RE43  2.2K_0402_5%  [R_0402]  203.9 84.46 270 top
RE48  10K_0402_5%  [R_0402]  206.12 100.33 270 top
RE51  10K_0402_5%  [R_0402]  205.87 101.68 180 top
RE55  100K_0402_5%  [R_0402]  205.23 100.33 270 top
RE56  10K_0402_5%  [R_0402]  192.48 95.18 180 top
RE57  1K_0402_5%  [R_0402]  205.11 82.24 270 top
RE58  100K_0402_5%  [R_0402]  206 82.24 270 top
RE60  43_0402_5%  [R_0402]  198.3 87.19 180 top
RE61  0_0402_5%  [R0402_0OHM]  209.24 84.39 270 top
RE62  100K_0402_5%  [R_0402]  211.04 83.85 270 top
RE63  100K_0402_5%  [R_0402]  206 79.1 90 top
RE64  4.7K_0402_5%  [R_0402]  201.63 82.48 180 top
RE65  100_0402_1%  [R_0402]  205.11 80.01 270 top
RE66  10_0402_5%  [R_0402]  203.14 99.32 90 top
RE67  10K_0402_5%  [R_0402]  194.96 81.4 180 top
RE68  100K_0402_5%  [R_0402]  194.93 84.83 0 top
RE69  8.2K_0402_5%  [R_0402]  200.22 101.48 270 top
RE70  2.2K_0402_5%  [R_0402]  199.28 102.3 180 top
RE71  49.9_0402_1%  [R_0402]  181.89 82.02 0 top
RE72  10K_0402_5%  [R_0402]  185.37 83.12 270 top
RE73  10K_0402_5%  [R_0402]  187.2 83.12 270 top
RE74  10K_0402_5%  [R_0402]  188.28 83.19 270 top
RE75  100K_0402_5%  [R_0402]  186.26 83.12 270 top
RE77  1.58K_0402_1%  [R_0402]  211.52 99.18 90 top
RE78  1K_0402_5%  [R_0402]  203.19 103.55 90 top
RE79  33K_0402_5%  [R_0402]  216.6 95.29 90 top
RE81  10K_0402_5%  [R_0402]  210.15 79.95 180 top
RE82  10K_0402_5%  [R_0402]  210.15 80.83 180 top
RE83  100K_0402_5%  [R_0402]  186.5 109.67 270 top
RE85  100K_0402_5%  [R_0402]  182.57 112 270 top
RE86  10K_0402_5%  [R_0402]  197.94 92.17 0 top
RE87  100K_0402_5%  [R_0402]  181.65 112 270 top
RE88  47K_0402_5%  [R_0402]  198.26 88.64 180 top
RE274  0_0402_5%  [R_0402]  197.35 89.53 0 top
RE275  0_0402_5%  [R0402_0OHM]  171.96 101.21 0 top
RE276  10K_0402_5%  [R_0402]  190.95 101.65 180 top
RE277  100K_0402_5%  [R_0402]  208.78 99.41 180 top
RE279  0_0402_5%  [R0402_0OHM]  212.9 83.27 90 top
RE280  0_0402_5%  [R_0402]  212.01 83.27 90 top
RE281  0_0402_5%  [R_0402]  207.61 101.68 180 top
RE282  0_0402_5%  [R0402_0OHM]  72.11 19.89 270 bottom
RE283  0_0402_5%  [R_0402]  216.56 86.67 270 top
RE284  2.2K_0402_5%  [R_0402]  199.28 103.19 180 top
RI4  2K_0402_1%  [R_0402]  223.4 77.64 180 top
RI13  10K_0402_5%  [R_0402]  62.07 117.03 270 top
RI14  22.1K_0402_1%  [R_0402]  57.36 120.55 270 top
RI16  4.7K_0402_5%  [R_0402]  219.26 85.97 0 top
RI18  4.7K_0402_5%  [R_0402]  219.26 84.19 0 top
RI19  4.7K_0402_5%  [R_0402]  219.26 78.84 0 top
RI20  4.7K_0402_5%  [R_0402]  220.17 86.85 180 top
RI22  4.7K_0402_5%  [R_0402]  220.17 85.08 180 top
RI23  4.7K_0402_5%  [R_0402]  220.17 79.74 180 top
RI24  4.7K_0402_5%  [R_0402]  220.17 82.41 180 top
RI25  4.7K_0402_5%  [R_0402]  219.26 83.29 0 top
RI34  4.7K_0402_5%  [R_0402]  219.26 80.63 0 top
RI35  4.7K_0402_5%  [R_0402]  220.17 81.53 180 top
RI36  4.7K_0402_5%  [R_0402]  229.31 81.92 180 top
RI37  4.7K_0402_5%  [R_0402]  228.4 82.8 0 top
RI38  4.7K_0402_5%  [R_0402]  222.84 86.45 270 top
RL1  10K_0402_5%  [R_0402]  206.62 121.29 270 top
RL2  10K_0402_5%  [R_0402]  205.74 121.29 270 top
RL3  0_0402_5%  [R0402_0OHM]  208.73 109.2 90 top
RL4  4.7K_0402_5%  [R_0402]  204.22 110.11 270 top
RL5  10K_0402_5%  [R_0402]  205.74 106.78 90 top
RL6  4.7K_0402_5%  [R_0402]  205.11 109.2 90 top
RL7  0_0402_5%  [R0402_0OHM]  206.63 106.78 90 top
RL8  0_0603_5%  [R0603_0OHM]  213.2 120.98 270 bottom
RL9  10K_0402_5%  [R_0402]  206.95 110.11 270 top
RL10  0_0402_5%  [R0402_0OHM]  209.62 109.2 90 top
RL11  1M_0402_5%  [R_0402]  210.51 110.11 270 top
RL12  1K_0402_5%  [R_0402]  210.14 120.32 90 top
RL13  3.01K_0402_1%  [R_0402]  213.12 109.99 270 top
RL14  150_0402_5%  [R_0402]  257.94 123.82 0 bottom
RL15  75_0402_1%  [R_0402]  279.71 123.17 270 top
RL16  75_0402_1%  [R_0402]  278.44 123.17 270 top
RL17  75_0402_1%  [R_0402]  270.82 123.17 270 top
RL18  75_0402_1%  [R_0402]  269.86 123.17 270 top
RL19  150_0402_5%  [R_0402]  257.94 122.86 0 bottom
RL20  150_0402_5%  [R_0402]  257.94 121.91 0 bottom
RL21  5.6_0603_5%  [R_0603]  220.41 119.6 90 bottom
RL22  5.6_0603_5%  [R_0603]  219.2 119.6 90 bottom
RL23  5.6_0603_5%  [R_0603]  217.97 119.65 90 bottom
RL24  5.6_0603_5%  [R_0603]  216.75 119.65 90 bottom
RL25  5.6_0603_5%  [R_0603]  213.39 115.74 0 top
RL26  5.6_0603_5%  [R_0603]  213.4 116.94 0 top
RL27  5.6_0603_5%  [R_0603]  213.4 118.15 0 top
RL28  5.6_0603_5%  [R_0603]  213.4 119.36 0 top
RL29  1M_0402_5%  [R_0402]  208.35 120.32 90 top
RL30  1M_0402_5%  [R_0402]  220.94 120.93 0 top
RN1  100K_0402_5%  [R_0402]  213.41 110.9 90 top
RN2  100K_0402_5%  [R_0402]  216.7 110.65 270 top
RN3  2.2K_0402_5%  [R_0402]  225.87 118.84 180 top
RN4  2.2K_0402_5%  [R_0402]  225.87 117.92 180 top
RN5  10K_0402_5%  [R_0402]  219.69 109.63 180 bottom
RN6  10K_0402_5%  [R_0402]  195.01 105.97 180 top
RN7  10K_0402_5%  [R_0402]  194.1 105.07 0 top
RPC1  10K_8P4R_5%  [RP_0804_8P4R]  163.3 66.65 180 top
RPC2  2.2K_0804_8P4R_5%  [RP_0804_8P4R]  138.25 95.22 90 top
RPC3  10K_8P4R_5%  [RP_0804_8P4R]  149.99 81.96 180 top
RPC4  10K_8P4R_5%  [RP_0804_8P4R]  145.88 96.35 270 top
RPC5  10K_8P4R_5%  [RP_0804_8P4R]  155.95 74.49 180 top
RPC6  10K_8P4R_5%  [RP_0804_8P4R]  147.16 82.03 180 bottom
RPC7  10K_8P4R_5%  [RP_0804_8P4R]  163.3 72.51 180 top
RPC8  10K_0804_8P4R_5%  [RP_0804_8P4R]  145.81 85.47 0 bottom
RPC9  10K_8P4R_5%  [RP_0804_8P4R]  149.99 79 180 top
RPC10  10K_8P4R_5%  [RP_0804_8P4R]  149.99 76.05 180 top
RPC11  33_0804_8P4R_5%  [RP_0804_8P4R]  175.25 73.21 180 top
RPC12  33_0804_8P4R_5%  [RP_0804_8P4R]  177.18 74.71 0 top
RPC14  2.2K_0804_8P4R_5%  [RP_0804_8P4R]  162.15 70.95 0 top
RPC15  10K_8P4R_5%  [RP_0804_8P4R]  143.27 98.08 90 top
RPC16  10K_8P4R_5%  [RP_0804_8P4R]  143.06 96.36 270 top
RPC17  10K_8P4R_5%  [RP_0804_8P4R]  152.88 79 180 top
RPC18  10K_8P4R_5%  [RP_0804_8P4R]  152.88 81.94 180 top
RPC19  10K_8P4R_5%  [RP_0804_8P4R]  151.73 77.55 0 top
RPC20  100K_0804_8P4R_5%  [RP_0804_8P4R]  139.75 95.23 90 bottom
RPC21  51_0804_8P4R_5%  [RP_0804_8P4R]  88.42 76.04 0 top
RPE2  4.7K_8P4R_5%  [RP_0804_8P4R]  196.47 96.37 0 top
RPE3  2.2K_0804_8P4R_5%  [RP_0804_8P4R]  215.08 89.09 180 top
RPE4  100K_0804_8P4R_5%  [RP_0804_8P4R]  174.06 95.7 180 top
RPE5  100K_0804_8P4R_5%  [RP_0804_8P4R]  213.88 87.58 0 top
RPE6  10K_8P4R_5%  [RP_0804_8P4R]  188.66 88.27 180 top
RPE7  10K_8P4R_5%  [RP_0804_8P4R]  183.33 83.49 180 top
RPE8  100K_0804_8P4R_5%  [RP_0804_8P4R]  181.03 91.66 270 top
RPE9  100K_0804_8P4R_5%  [RP_0804_8P4R]  194.69 103.7 0 top
RPE10  100K_0804_8P4R_5%  [RP_0804_8P4R]  204.87 103.37 90 top
RPV1  2.2K_0804_8P4R_5%  [RP_0804_8P4R]  144.57 119.38 180 bottom
RPV2  2.2K_0804_8P4R_5%  [RP_0804_8P4R]  162.97 116.37 0 bottom
RR1  10_0402_5%  [R_0402]  27.61 20.44 0 top
RR2  191_0402_1%  [R_0402]  25.47 25.63 90 top
RR3  0_0402_5%  [R0402_0OHM]  27.61 21.39 0 top
RR4  0_0402_5%  [R0402_0OHM]  27.61 22.34 0 top
RR5  4.7K_0402_1%  [R_0402]  20.08 13.85 180 top
RR6  100K_0402_5%  [R_0402]  16.31 18.85 0 top
RR8  100K_0402_5%  [R_0402]  17.22 19.73 180 top
RR11  1M_0402_5%  [R_0402]  32.62 13.82 270 top
RR15  10K_0402_5%  [R_0402]  16.51 22.42 270 top
RV1  4.7K_0402_5%  [R_0402]  100.22 117.4 180 top
RV2  4.7K_0402_5%  [R_0402]  102.11 113.71 90 top
RV3  100K_0402_5%  [R_0402]  76.52 118.93 0 top
RV4  270K_0402_5%  [R_0402]  88.08 113.13 90 top
RV5  47K_0402_5%  [R_0402]  87.06 114.05 270 top
RV6  47K_0402_5%  [R_0402]  123.18 124.58 0 bottom
RV7  2.2K_0402_5%  [R_0402]  91.68 127.89 270 bottom
RV8  10K_0402_5%  [R_0402]  86.68 127.89 270 bottom
RV9  2.2K_0402_5%  [R_0402]  92.64 127.89 270 bottom
RV14  2.2K_0402_5%  [R_0402]  143.75 116.68 180 bottom
RV15  2.2K_0402_5%  [R_0402]  143.75 115.79 180 bottom
RV50  4.99K_0402_1%  [R_0402]  125.03 111.45 270 top
RV51  4.7K_0402_5%  [R_0402]  127.71 123.22 270 top
RV52  4.7K_0402_5%  [R_0402]  126.82 122.3 90 top
RV54  4.7K_0402_5%  [R_0402]  129.24 112.58 180 top
RV55  4.7K_0402_5%  [R_0402]  124.15 110.53 90 top
RV56  4.7K_0402_5%  [R_0402]  121.34 110.53 90 top
RV57  4.7K_0402_5%  [R_0402]  121.43 123.22 270 top
RV58  4.7K_0402_5%  [R_0402]  114.68 116.08 0 top
RV60  4.7K_0402_5%  [R_0402]  116.75 120.57 0 top
RV61  4.7K_0402_5%  [R_0402]  128.32 113.47 0 top
RV62  4.7K_0402_5%  [R_0402]  123.26 111.45 270 top
RV63  4.7K_0402_5%  [R_0402]  123.08 125.15 0 top
RV64  4.7K_0402_5%  [R_0402]  122.24 111.45 270 top
RV65  4.7K_0402_5%  [R_0402]  115.6 117.01 180 top
RV66  4.7K_0402_5%  [R_0402]  117.66 121.47 180 top
RV67  1M_0402_5%  [R_0402]  129.43 120.96 180 top
RV68  100K_0402_5%  [R_0402]  114.56 114.27 0 top
RV73  1M_0402_5%  [R_0402]  145.24 107.5 180 bottom
RV74  1M_0402_5%  [R_0402]  159.12 116.51 0 bottom
RV75  1M_0402_5%  [R_0402]  149.04 119.93 90 bottom
RV76  150_0402_1%  [R_0402]  156.42 128.51 90 top
RV77  150_0402_1%  [R_0402]  157.33 128.53 90 top
RV78  150_0402_1%  [R_0402]  152.35 128.26 90 top
RV79  100K_0402_5%  [R_0402]  159.64 109.79 270 bottom
RV80  1M_0402_5%  [R_0402]  145.48 103.93 90 bottom
RV81  2.2K_0402_5%  [R_0402]  144.57 105.71 0 bottom
RV82  1M_0402_5%  [R_0402]  149.93 119.93 90 bottom
RV83  2.2K_0402_5%  [R_0402]  157.29 104.71 270 bottom
RV84  1M_0402_5%  [R_0402]  158.18 104.71 270 bottom
RV85  1M_0402_5%  [R_0402]  159.12 115.62 0 bottom
RV86  10K_0402_5%  [R_0402]  152.78 96.36 180 bottom
RV87  2.2K_0402_5%  [R_0402]  159.73 98.56 180 bottom
RV88  10K_0402_5%  [R_0402]  144.33 108.4 0 bottom
RV89  3.74K_0402_1%  [R_0402]  145.3 110.42 180 bottom
RV90  100K_0402_5%  [R_0402]  136.68 126.71 270 top
RV91  100K_0402_5%  [R_0402]  160.77 99.71 270 bottom
RV100  4.7K_0402_5%  [R_0402]  134.17 120.4 0 top
RV501  100K_0402_5%  [R_0402]  250.82 125.06 90 bottom
RV502  100K_0402_5%  [R_0402]  249.94 125.06 90 bottom
RV503  5.1M_0402_5%  [R_0402]  248.22 125.03 90 bottom
RV504  1M_0402_5%  [R_0402]  247.32 125.95 270 bottom
RV505  100K_0402_5%  [R_0402]  246.43 125.03 90 bottom
RV507  100K_0402_5%  [R_0402]  240.05 127.12 180 top
RV508  1M_0402_5%  [R_0402]  142.59 123.96 180 bottom
RV509  1M_0402_5%  [R_0402]  142.59 125.23 180 bottom
RV516  2.2K_0402_5%  [R_0402]  159.64 110.63 90 bottom
RV517  2.2K_0402_5%  [R_0402]  158.74 107.28 180 top
RV518  2.2K_0402_5%  [R_0402]  156.73 120.74 270 bottom
RV519  2.2K_0402_5%  [R_0402]  157.63 120.74 270 bottom
RV550  4.7K_0402_5%  [R_0402]  125.94 122.3 90 top
RV551  4.7K_0402_5%  [R_0402]  125.05 123.22 270 top
RV554  100K_0402_5%  [R_0402]  119.59 123.22 270 top
RV555  100K_0402_5%  [R_0402]  120.54 123.22 270 top
RV600  4.99K_0402_1%  [R_0402]  136.48 112.01 270 top
RV601  4.7K_0402_5%  [R_0402]  134.46 121.57 0 top
RV602  4.7K_0402_5%  [R_0402]  130.61 112.58 0 top
RV603  4.7K_0402_5%  [R_0402]  135.99 120.4 0 top
RV604  100K_0402_5%  [R_0402]  142.55 109.7 90 top
RV605  100K_0402_5%  [R_0402]  140.81 109.7 90 top
RV606  1M_0402_5%  [R_0402]  146.08 117.82 180 top
RV607  1M_0402_5%  [R_0402]  146.03 113.88 180 top
RV608  100K_0402_5%  [R_0402]  141.68 109.7 90 top
RV609  100K_0402_5%  [R_0402]  139.93 109.7 90 top
RV610  4.7K_0402_5%  [R_0402]  128.53 119.94 0 top
RV611  4.7K_0402_5%  [R_0402]  142.43 127.38 270 top
RV612  4.7K_0402_5%  [R_0402]  141.53 127.37 270 top
RV613  4.7K_0402_5%  [R_0402]  140.62 127.37 270 top
RV614  4.7K_0402_5%  [R_0402]  139.7 127.37 270 top
RV615  4.7K_0402_5%  [R_0402]  133.3 121.57 270 top
RV616  4.7K_0402_5%  [R_0402]  130.29 119.94 0 top
RV617  4.7K_0402_5%  [R_0402]  143.32 126.47 90 top
RV618  4.7K_0402_5%  [R_0402]  142.83 122.94 90 top
RV619  4.7K_0402_5%  [R_0402]  141.91 122.94 90 top
RV620  4.7K_0402_5%  [R_0402]  140.77 122.94 90 top
RV701  100K_0402_5%  [R_0402]  172.06 117.81 270 bottom
RV702  10_0402_5%  [R_0402]  166.65 117.96 0 bottom
RZ5  100K_0402_5%  [R_0402]  166.6 78.22 180 top
RZ8  2.2K_0402_5%  [R_0402]  218.06 47.87 270 top
RZ9  2.2K_0402_5%  [R_0402]  218.98 47.87 270 top
RZ10  1M_0402_5%  [R_0402]  225.35 47.81 270 top
RZ14  100K_0402_5%  [R_0402]  163.53 92.64 180 bottom
RZ15  100K_0402_5%  [R_0402]  161.85 89.59 0 bottom
RZ16  100K_0402_5%  [R_0402]  164.21 82.97 0 top
RZ17  0_0402_5%  [R0402_0OHM]  190.92 57.48 180 top
RZ18  4.7K_0402_5%  [R_0402]  202.43 58.31 0 top
RZ19  4.7K_0402_5%  [R_0402]  205.12 58.31 180 top
RZ21  33_0402_5%  [R_0402]  191.26 81.78 180 top
RZ22  10K_0402_5%  [R_0402]  185.59 84.15 90 top
RZ24  10K_0402_5%  [R_0402]  194.06 116.26 90 top
RZ25  390_0402_5%  [R_0402]  189.3 120.32 270 top
RZ26  33_0402_5%  [R_0402]  190.92 56.61 180 top
RZ27  220_0402_5%  [R_0402]  192.69 112.65 270 top
RZ28  330_0402_5%  [R_0402]  192.53 121.34 0 top
RZ29  33_0402_5%  [R_0402]  190.92 58.36 180 top
RZ30  33_0402_5%  [R_0402]  189.51 61.73 270 top
RZ31  100K_0402_5%  [R_0402]  194.06 115.31 270 top
RZ32  150_0402_5%  [R_0402]  190.88 125.66 270 top
RZ33  390_0402_5%  [R_0402]  200.09 122.16 0 top
RZ34  220_0402_5%  [R_0402]  195.01 125.66 0 top
RZ35  33_0402_5%  [R_0402]  190.92 55.72 180 top
RZ36  150_0402_5%  [R_0402]  196.61 117.55 270 top
RZ37  100K_0402_5%  [R_0402]  206.03 55.83 0 bottom
RZ38  100K_0402_5%  [R_0402]  191.87 41.72 90 top
RZ39  10K_0402_5%  [R_0402]  207.77 55.83 0 bottom
RZ40  100K_0402_5%  [R_0402]  192.76 41.72 90 top
RZ41  0_0402_5%  [R_0402]  186.24 63.14 90 bottom
RZ42  0_0402_5%  [R0402_0OHM]  188.01 63.12 90 bottom
RZ43  390_0402_5%  [R_0402]  190.88 117.02 180 top
RZ44  390_0402_5%  [R_0402]  189.17 121.66 180 top
RZ46  0_0603_5%  [R_0603]  196.82 37.68 90 top
RZ47  0_0603_5%  [R0603_0OHM]  200.09 37.67 90 top
RZ50  0_0402_5%  [R0402_0OHM]  199.68 62.58 270 bottom
RZ51  0_0402_5%  [R0402_0OHM]  171.22 77.26 90 top
RZ52  0.01_1206_1%  [R_1206]  135.79 102.24 90 top
RZ53  0_0603_5%  [R0603_0OHM]  137.11 100.56 180 top
RZ56  0_0402_5%  [R_0402]  180.01 109.82 90 top
RZ57  0_0402_5%  [R0402_0OHM]  179.11 109.82 90 top
ST1  -  [CLIP_C5P5]  80 121.25 180 bottom
ST2  -  [CLIP_C5P5]  50.5 128.65 0 top
ST3  -  [CLIP_C5P5]  281.93 130.45 0 top
SW1  SS3-CMFTQR9_3P  [SW_SS3-CMFTQR9_3P]  122.99 14.59 0 bottom
SW2  SKRBAAE010_4P~D  [SW_SKRBAAE010_4P]  226.13 94.42 180 top
T8  PAD~D  [TPC12]  135.94 71.54 0 top
T9  PAD~D  [TPC12]  141.56 75.21 0 top
T10  PAD~D  [TPC12]  92.31 84.1 0 top
T11  PAD~D  [TPC12]  90.85 84.64 0 top
T12  PAD~D  [TPC12]  100.27 93.4 0 top
T13  PAD~D  [TPC12]  93.6 92.43 0 top
T14  PAD~D  [TPC12]  93.68 83.38 0 top
T15  PAD~D  [TPC12]  98.81 93.88 0 top
T16  PAD~D  [TPC12]  137.63 76.08 0 top
